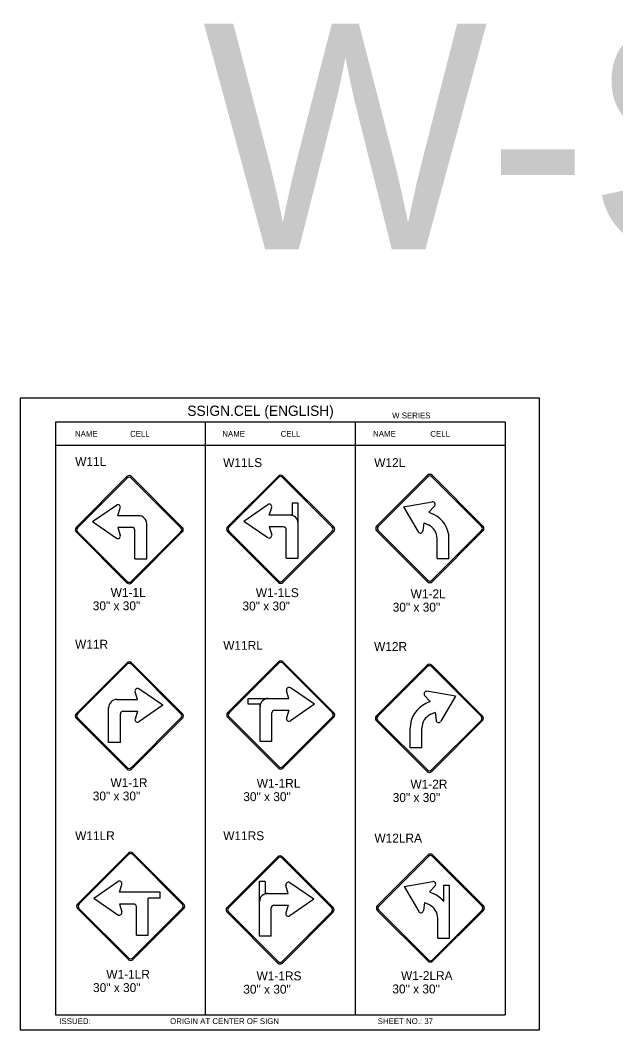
# Model space of a CAD drawing. Extents: x -5299 to 22597, y -19549 to -1808.
# Drawn here: x 121 to 925, y -3623 to -2261 of the extents above; entities that cross this region are included whole.
import ezdxf

# ---------------------------------------------------------------- set-up
doc = ezdxf.new("R2010")
doc.units = 0
for name, color, linetype in [('Level 1', 7, 'Continuous'), ('Level 2', 7, 'Continuous'), ('Level 3', 7, 'Continuous'), ('Level 62', 7, 'Continuous')]:
    doc.layers.add(name, color=color, linetype=linetype)

msp = doc.modelspace()

# ---------------------------------------------------------------- linework, layer by layer
at = {"layer": 'Level 1'}
for p, q in [((775.8, -2802.9), (168.7, -2802.9)), ((168.7, -2802.9), (168.7, -3602.9)), ((371.1, -2802.9), (371.1, -3602.9)), ((573.4, -2802.9), (573.4, -3602.9)), ((775.8, -2802.9), (775.8, -3602.9)), ((371.1, -2834.6), (168.7, -2834.6)), ((573.4, -2834.6), (371.1, -2834.6)), ((775.8, -2834.6), (573.4, -2834.6)), ((198.6, -2945.5), (265.6, -2878.5)), ((271.1, -2878.5), (338.2, -2945.5)), ((402.9, -2944.8), (470, -2877.8)), ((475.4, -2877.8), (542.5, -2944.8)), ((604.4, -2943.9), (671.4, -2876.8)), ((676.9, -2876.8), (743.9, -2943.9)), ((218.7, -2937.2), (251.1, -2914.9)), ((423, -2936.5), (455.4, -2914.2)), ((488.4, -2912.6), (488.4, -2928.6)), ((496.3, -2912.6), (488.4, -2912.6)), ((496.3, -2986.5), (496.3, -2912.6)), ((638.6, -2917.3), (677.4, -2910.7)), ((253.1, -2929.3), (256.4, -2918.9)), ((281, -2929.3), (253.1, -2929.3)), ((457.5, -2928.6), (460.7, -2918.1)), ((488.4, -2928.6), (457.5, -2928.6)), ((638.6, -2917.3), (658.5, -2951.3)), ((673, -2924.6), (680.4, -2916.5)), ((673, -2924.6), (678.8, -2927.3)), ((218.7, -2937.2), (251.1, -2959.7)), ((292, -2987.3), (292, -2940.2)), ((423, -2936.5), (455.4, -2958.9)), ((666.3, -2939), (664.9, -2949.9)), ((666.3, -2939), (672.3, -2941.8)), ((265.6, -3018), (198.6, -2951)), ((272.4, -2945.2), (253.1, -2945.2)), ((253.1, -2945.2), (256.4, -2955.7)), ((268.8, -2948), (268.8, -2948)), ((338.2, -2951), (271.1, -3018)), ((276.1, -2987.3), (276.1, -2948.9)), ((470, -3017.3), (402.9, -2950.3)), ((476.7, -2944.5), (457.5, -2944.5)), ((457.5, -2944.5), (460.7, -2955)), ((473.1, -2947.3), (473.1, -2947.3)), ((542.5, -2950.3), (475.4, -3017.3)), ((480.4, -2986.5), (480.4, -2948.2)), ((671.4, -3016.4), (604.4, -2949.3)), ((674.6, -2946.3), (674.6, -2946.3)), ((743.9, -2949.3), (676.9, -3016.4)), ((684.1, -2987.1), (684.1, -2960.2)), ((699.9, -2987.1), (699.9, -2960.3)), ((276.1, -2987.3), (292, -2987.3)), ((480.4, -2986.5), (496.3, -2986.5)), ((684.1, -2987.1), (699.9, -2987.1)), ((198.8, -3196.8), (265.8, -3129.8)), ((271.3, -3129.8), (338.3, -3196.8)), ((403.2, -3195.4), (470.2, -3128.4)), ((475.7, -3128.4), (542.7, -3195.4)), ((603.9, -3200), (670.9, -3133)), ((676.4, -3133), (743.4, -3200)), ((279.5, -3177.3), (276.3, -3166.8)), ((313.9, -3185.2), (281.5, -3162.9)), ((483.9, -3175.9), (480.7, -3165.5)), ((518.3, -3183.8), (485.9, -3161.5)), ((674.5, -3180.2), (667.1, -3172.1)), ((708.9, -3172.9), (670.1, -3166.3)), ((708.9, -3172.9), (689, -3206.8)), ((240.6, -3235.2), (240.6, -3188.1)), ((251.6, -3177.3), (279.5, -3177.3)), ((313.9, -3185.2), (281.5, -3207.6)), ((429, -3175.9), (483.9, -3175.9)), ((429, -3183.8), (429, -3175.9)), ((445.1, -3183.8), (429, -3183.8)), ((445.1, -3233.9), (445.1, -3183.8)), ((518.3, -3183.8), (485.9, -3206.3)), ((674.5, -3180.2), (668.7, -3182.9)), ((256.6, -3235.2), (256.6, -3196.9)), ((260.2, -3193.2), (279.5, -3193.2)), ((268.9, -3199.3), (268.9, -3199.3)), ((279.5, -3193.2), (276.3, -3203.7)), ((470.2, -3267.9), (403.2, -3200.9)), ((461, -3233.9), (461, -3195.5)), ((464.6, -3191.9), (483.9, -3191.9)), ((473.3, -3197.9), (473.3, -3197.9)), ((542.7, -3200.9), (475.7, -3267.9)), ((483.9, -3191.9), (480.7, -3202.3)), ((681.2, -3194.7), (675.2, -3197.4)), ((681.2, -3194.7), (682.6, -3205.4)), ((265.8, -3269.3), (198.8, -3202.3)), ((338.3, -3202.3), (271.3, -3269.3)), ((670.9, -3272.5), (603.9, -3205.5)), ((674.1, -3202.5), (674.1, -3202.5)), ((743.4, -3205.5), (676.4, -3272.5)), ((647.6, -3242.8), (647.6, -3216)), ((663.5, -3242.8), (663.5, -3215.9)), ((256.6, -3235.2), (240.6, -3235.2)), ((461, -3233.9), (445.1, -3233.9)), ((663.5, -3242.8), (647.6, -3242.8)), ((200.6, -3453.7), (267.6, -3386.7)), ((273.1, -3386.7), (340.1, -3453.7)), ((402.3, -3458.5), (469.4, -3391.5)), ((474.9, -3391.5), (541.9, -3458.5)), ((605.2, -3456.2), (672.3, -3389.2)), ((677.7, -3389.2), (744.8, -3456.2)), ((220.7, -3445.4), (253.1, -3423.1)), ((255.1, -3437.5), (258.4, -3427)), ((444.2, -3496.9), (444.2, -3423)), ((452.1, -3423), (444.2, -3423)), ((452.1, -3423), (452.1, -3439)), ((483.1, -3439), (479.8, -3428.5)), ((517.5, -3446.9), (485.1, -3424.6)), ((639.4, -3429.6), (678.2, -3423)), ((639.4, -3429.6), (659.3, -3463.6)), ((673.8, -3436.9), (681.2, -3428.8)), ((692.9, -3449.8), (692.9, -3428)), ((692.9, -3428), (700.7, -3428)), ((700.7, -3499.5), (700.7, -3428)), ((220.7, -3445.4), (253.1, -3467.8)), ((310, -3437.5), (255.1, -3437.5)), ((294, -3495.4), (294, -3445.4)), ((310, -3445.4), (294, -3445.4)), ((310, -3445.4), (310, -3437.5)), ((452.1, -3439), (483.1, -3439)), ((517.5, -3446.9), (485.1, -3469.3)), ((673.8, -3436.9), (679.6, -3439.6)), ((267.6, -3526.2), (200.6, -3459.2)), ((274.4, -3453.4), (255.1, -3453.4)), ((255.1, -3453.4), (258.4, -3463.9)), ((270.8, -3456.2), (270.8, -3456.2)), ((340.1, -3459.2), (273.1, -3526.2)), ((278.1, -3495.4), (278.1, -3457.1)), ((460.2, -3496.9), (460.2, -3458.6)), ((463.8, -3454.9), (483.1, -3454.9)), ((483.1, -3454.9), (479.8, -3465.4)), ((667.1, -3451.4), (665.7, -3462.2)), ((667.1, -3451.4), (673.1, -3454.1)), ((675.4, -3458.7), (675.4, -3458.7)), ((469.4, -3531), (402.3, -3464)), ((472.5, -3461), (472.5, -3461)), ((541.9, -3464), (474.9, -3531)), ((672.3, -3528.7), (605.2, -3461.7)), ((744.8, -3461.7), (677.7, -3528.7)), ((684.9, -3499.5), (684.9, -3472.6)), ((278.1, -3495.4), (294, -3495.4)), ((460.2, -3496.9), (444.2, -3496.9)), ((684.9, -3499.5), (700.7, -3499.5)), ((168.7, -3602.9), (775.8, -3602.9))]:
    msp.add_line(p, q, dxfattribs=at)
for centre, radius, start, end in [((268.4, -2881.2), 3.88, 45, 135), ((472.7, -2880.5), 3.88, 45, 135), ((674.2, -2879.6), 3.88, 45, 135), ((253, -2917.9), 3.52, 343.8088, 121.6584), ((457.3, -2917.1), 3.52, 343.8088, 121.6584), ((677.8, -2914.2), 3.51, 318.677, 97.1175), ((281.1, -2940.2), 10.9, 0, 90), ((485.4, -2939.5), 10.9, 0, 90), ((663.6, -2960.3), 36.4, 359.9807, 65.3304), ((663.5, -2960.3), 20.5, 0.0924, 64.7362), ((201.4, -2948.3), 3.88, 135, 225), ((253, -2956.7), 3.52, 238.3416, 16.1912), ((272.4, -2948.8), 3.63, 0, 90), ((335.4, -2948.3), 3.88, 315, 45), ((405.7, -2947.5), 3.88, 135, 225), ((457.3, -2955.9), 3.52, 238.3416, 16.1912), ((476.7, -2948.1), 3.63, 0, 90), ((539.7, -2947.5), 3.88, 315, 45), ((607.2, -2946.6), 3.88, 135, 225), ((661.4, -2949.3), 3.52, 213.1885, 351.7617), ((741.2, -2946.6), 3.88, 315, 45), ((268.4, -3015.3), 3.88, 225, 315), ((472.7, -3014.6), 3.88, 225, 315), ((674.2, -3013.6), 3.88, 225, 315), ((268.5, -3132.5), 3.88, 45, 135), ((472.9, -3131.1), 3.88, 45, 135), ((673.7, -3135.7), 3.88, 45, 135), ((484.1, -3164.5), 3.52, 58.3416, 196.1912), ((279.7, -3165.8), 3.52, 58.3416, 196.1912), ((669.8, -3169.8), 3.51, 82.8825, 221.323), ((251.6, -3188.2), 10.9, 90, 180), ((456, -3186.8), 10.9, 90, 180), ((684, -3215.9), 36.4, 114.6696, 180.0193), ((201.5, -3199.5), 3.88, 135, 225), ((260.2, -3196.8), 3.63, 90, 180), ((335.6, -3199.5), 3.88, 315, 45), ((405.9, -3198.2), 3.88, 135, 225), ((464.6, -3195.5), 3.63, 90, 180), ((540, -3198.2), 3.88, 315, 45), ((606.6, -3202.7), 3.88, 135, 225), ((684, -3215.9), 20.5, 115.2638, 179.9076), ((740.7, -3202.7), 3.88, 315, 45), ((279.7, -3204.6), 3.52, 163.8088, 301.6584), ((484.1, -3203.3), 3.52, 163.8088, 301.6584), ((686.1, -3205), 3.52, 188.2383, 326.8115), ((268.5, -3266.5), 3.88, 225, 315), ((472.9, -3265.2), 3.88, 225, 315), ((673.7, -3269.7), 3.88, 225, 315), ((270.4, -3389.4), 3.88, 45, 135), ((472.1, -3394.2), 3.88, 45, 135), ((675, -3391.9), 3.88, 45, 135), ((254.9, -3426), 3.52, 343.8088, 121.6584), ((483.3, -3427.5), 3.52, 58.3416, 196.1912), ((678.6, -3426.5), 3.51, 318.677, 97.1175), ((455.2, -3449.9), 10.9, 90, 180), ((664.4, -3472.6), 36.4, 38.3789, 65.3304), ((203.4, -3456.4), 3.88, 135, 225), ((274.4, -3457), 3.63, 0, 90), ((337.4, -3456.5), 3.88, 315, 45), ((405.1, -3461.2), 3.88, 135, 225), ((463.8, -3458.5), 3.63, 90, 180), ((539.1, -3461.2), 3.88, 315, 45), ((608, -3458.9), 3.88, 135, 225), ((664.3, -3472.7), 20.5, 0.0924, 64.7362), ((742, -3458.9), 3.88, 315, 45), ((254.9, -3464.8), 3.52, 238.3416, 16.1912), ((483.3, -3466.3), 3.52, 163.8088, 301.6584), ((662.2, -3461.7), 3.52, 213.1885, 351.7617), ((270.4, -3523.5), 3.88, 225, 315), ((675, -3526), 3.88, 225, 315), ((472.1, -3528.3), 3.88, 225, 315)]:
    msp.add_arc(centre, radius, start, end, dxfattribs=at)
at = {"layer": 'Level 3'}
for p, q in [((602.4, -2943.6), (671.2, -2874.8)), ((677.2, -2874.8), (745.9, -2943.6)), ((265.4, -2876.5), (196.6, -2945.3)), ((340.1, -2945.3), (271.4, -2876.5)), ((469.7, -2875.8), (400.9, -2944.5)), ((544.5, -2944.5), (475.7, -2875.8)), ((196.6, -2951.3), (265.4, -3020)), ((271.4, -3020), (340.1, -2951.3)), ((400.9, -2950.5), (469.7, -3019.3)), ((475.7, -3019.3), (544.5, -2950.5)), ((671.2, -3018.4), (602.4, -2949.6)), ((745.9, -2949.6), (677.2, -3018.4)), ((265.5, -3127.8), (196.8, -3196.5)), ((340.3, -3196.5), (271.5, -3127.8)), ((401.2, -3195.2), (469.9, -3126.4)), ((475.9, -3126.4), (544.7, -3195.2)), ((601.9, -3199.7), (670.7, -3131)), ((676.7, -3131), (745.4, -3199.7)), ((470, -3269.9), (401.2, -3201.1)), ((544.7, -3201.1), (475.9, -3269.9)), ((196.8, -3202.5), (265.5, -3271.3)), ((271.5, -3271.3), (340.3, -3202.5)), ((670.7, -3274.5), (601.9, -3205.7)), ((745.4, -3205.7), (676.7, -3274.5)), ((267.4, -3384.7), (198.6, -3453.5)), ((342.1, -3453.5), (273.4, -3384.7)), ((469.1, -3389.5), (400.4, -3458.2)), ((543.9, -3458.2), (475.1, -3389.5)), ((603.2, -3456), (672, -3387.2)), ((678, -3387.2), (746.8, -3456)), ((198.6, -3459.4), (267.4, -3528.2)), ((273.4, -3528.2), (342.1, -3459.4)), ((400.4, -3464.2), (469.1, -3533)), ((475.1, -3533), (543.9, -3464.2)), ((672, -3530.7), (603.2, -3461.9)), ((746.8, -3461.9), (678, -3530.7))]:
    msp.add_line(p, q, dxfattribs=at)
for centre, start, end in [((472.7, -2878.8), 45, 135), ((674.2, -2877.8), 45, 135), ((268.4, -2879.5), 45, 135), ((199.6, -2948.3), 135, 225), ((337.2, -2948.3), 315, 45), ((403.9, -2947.5), 135, 225), ((541.5, -2947.5), 315, 45), ((605.4, -2946.6), 135, 225), ((743, -2946.6), 315, 45), ((268.4, -3017), 225, 315), ((472.7, -3016.3), 225, 315), ((674.2, -3015.4), 225, 315), ((268.5, -3130.7), 45, 135), ((472.9, -3129.4), 45, 135), ((673.7, -3134), 45, 135), ((199.8, -3199.5), 135, 225), ((337.3, -3199.5), 315, 45), ((404.2, -3198.2), 135, 225), ((541.7, -3198.2), 315, 45), ((604.9, -3202.7), 135, 225), ((742.4, -3202.7), 315, 45), ((472.9, -3266.9), 225, 315), ((268.5, -3268.3), 225, 315), ((673.7, -3271.5), 225, 315), ((270.4, -3387.7), 45, 135), ((472.1, -3392.5), 45, 135), ((675, -3390.2), 45, 135), ((201.6, -3456.4), 135, 225), ((339.2, -3456.5), 315, 45), ((403.3, -3461.2), 135, 225), ((540.9, -3461.2), 315, 45), ((606.2, -3458.9), 135, 225), ((743.8, -3458.9), 315, 45), ((270.4, -3525.2), 225, 315), ((472.1, -3530), 225, 315), ((675, -3527.7), 225, 315)]:
    msp.add_arc(centre, 4.23, start, end, dxfattribs=at)
at = {"layer": 'Level 62'}
msp.add_lwpolyline([(121.2, -3623.1), (822.3, -3623.1), (822.3, -2770.8), (121.2, -2770.8)], close=True, dxfattribs=at)

# ---------------------------------------------------------------- texts
at = {"layer": 'Level 2'}
for s, p in [('W11L', (195.5, -2862.2)), ('W11LS', (395.2, -2863.7)), ('W12L', (599.1, -2863.7)), ('W11R', (195.3, -3108.8)), ('W11RL', (395.3, -3110.3)), ('W12R', (598.9, -3111.8)), ('W11LR', (195.4, -3367.2)), ('W11RS', (395.3, -3367.2)), ('W12LRA', (599.4, -3370.4))]:
    msp.add_text(s, height=12, dxfattribs=at).set_placement(p)
at = {"layer": 'Level 3'}
for s, height, p in [('W-SERIES CELLS', 304.775, (367.5, -2569.9)), ('SSIGN.CEL (ENGLISH)', 13.857, (346.8, -2794.6)), ('W SERIES', 7.92, (623.3, -2798)), ('NAME', 7.92, (195.2, -2822.8)), ('CELL', 7.92, (269.6, -2822.8)), ('NAME', 7.92, (394.1, -2822.8)), ('CELL', 7.92, (472.9, -2822.8)), ('NAME', 7.92, (597.6, -2822.8)), ('CELL', 7.92, (674.8, -2822.8)), ('W1-1L', 12, (243.4, -3038.9)), ('W1-1LS', 12, (439.3, -3039.2)), ('W1-2L', 12, (648.3, -3040.8)), ('30" x 30"', 12, (219.2, -3056.9)), ('30" x 30"', 12, (421.3, -3057.2)), ('30" x 30"', 12, (624.1, -3058.8)), ('W1-1R', 12, (243.1, -3295.6)), ('W1-1RL', 12, (440.6, -3296.5)), ('W1-2R', 12, (648, -3297.6)), ('30" x 30"', 12, (219.2, -3313.6)), ('30" x 30"', 12, (422.4, -3314.5)), ('30" x 30"', 12, (624.1, -3315.6)), ('W1-1LR', 12, (237.5, -3554.2)), ('W1-1RS', 12, (440.3, -3556.4)), ('W1-2LRA', 12, (635.3, -3556)), ('30" x 30"', 12, (219.6, -3572.2)), ('30" x 30"', 12, (422.4, -3574.4)), ('30" x 30"', 12, (623.6, -3574)), ('ISSUED:', 7.92, (174.1, -3615.4)), ('ORIGIN AT CENTER OF SIGN', 7.918, (323.6, -3615.4)), ('SHEET NO.: 37', 7.918, (603.8, -3615.4))]:
    msp.add_text(s, height=height, dxfattribs=at).set_placement(p)

doc.saveas('drawing.dxf')
